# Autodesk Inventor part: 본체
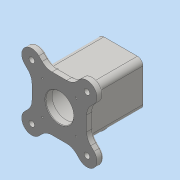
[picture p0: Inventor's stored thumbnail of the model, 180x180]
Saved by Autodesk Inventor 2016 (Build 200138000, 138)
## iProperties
Created: 2019-11
Part Number: 본체
Material: 일반
Document SubType Name: Modeling
Designer: user
Density: 1 g/cm^3
Appearance: 기본값
Author: user
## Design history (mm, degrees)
sketch "스케치1"
  geometry: L1 (49.497, 49.497)-(-49.497, -49.497); L2 (36.77, 62.225)-(-62.225, -36.77); L3 (-36.77, -62.225)-(62.225, 36.77); L4 (-49.497, 49.497)-(49.497, -49.497); L5 (-62.225, 36.77)-(36.77, -62.225); L6 (62.225, -36.77)-(-36.77, 62.225); L7 (0, 0)-(0, -25.456); L8 (49, 49)-(-49, 49); L9 (-49, 49)-(-49, -49); L10 (-49, -49)-(49, -49); L11 (49, -49)-(49, 49); L12 (49, 49)-(-49, -49); L13 (-49, 49)-(49, -49); A1 r 18 centre (49.497, 49.497) between (62.225, 36.77) and (36.77, 62.225); A2 r 18 centre (-49.497, -49.497) between (-62.225, -36.77) and (-36.77, -62.225); A3 r 18 centre (-49.497, 49.497) between (-36.77, 62.225) and (-62.225, 36.77); A4 r 18 centre (49.497, -49.497) between (36.77, -62.225) and (62.225, -36.77)
  constraints: 30 end point, 8 point on circle, 8 tangent, 4 centre point, 4 midpoint, 4 parallel, 1 horizontal, 1 perpendicular, 1 point on line, 1 vertical
  dimensions: "d0" = 70 distance of L7.start L1.end; "d1" = 36 diameter of A2; "d2" = 70 distance of L7.start L4.end; "d3" = 36 diameter of A4; "d4" = 90 deg angle of L4 L1; "d5" = 45 deg angle of L7 L1; "d6" = 98 distance of L9.end L10.end; "d7" = 98 distance of L8.end L9.end
extrude "돌출1" new body sketch "스케치1" distance "d8" = 12; taper "d9" = 0 deg
sketch "스케치2"
  geometry: L1 (-30, -40)-(30, -40); L2 (40, -30)-(40, 30); L3 (30, 40)-(-30, 40); L4 (-40, 30)-(-40, -30); L5 (-40, -40)-(40, 40); L6 (40, -40)-(-40, 40); A1 r 10 centre (-30, 30) between (-30, 40) and (-40, 30); A2 r 10 centre (-30, -30) between (-40, -30) and (-30, -40); A3 r 10 centre (30, -30) between (30, -40) and (40, -30); A4 r 10 centre (30, 30) between (40, 30) and (30, 40); 1 further point
  constraints: 12 end point, 8 point on circle, 8 point on line, 8 tangent, 4 centre point, 3 equal radius, 2 midpoint, 2 parallel, 1 horizontal, 1 perpendicular
  dimensions: "d10" = 80 distance of L6.end L5.end; "d11" = 80 distance of L6.start L5.end; "d56" = 10 radius of A1
extrude "돌출2" join sketch "스케치2" distance "d12" = 98; taper "d13" = 0 deg
sketch "스케치3"
  geometry: 2 further points
  constraints: 1 coincident
hole "구멍1" sketch "스케치3" at (0, 0) diameter "d14" = 50; stored, may be unused: countersink angle "d18" = 90 deg, drill point angle "d20" = 0 deg; dims "d15" = 6, "d16" = 4, "d17" = 2, "d19" = 12
sketch "스케치4"
  geometry: 2 further points
  constraints: 1 coincident
hole "구멍2" sketch "스케치4" at (0, 0) diameter "d21" = 50; stored, may be unused: countersink angle "d25" = 90 deg, drill point angle "d27" = 0 deg; dims "d22" = 6, "d23" = 70, "d24" = 86, "d26" = 12
node "작업 평면1"
sketch "스케치6"
  geometry: L1 (-23.544, 0)-(23.544, 0) reference; C1 r 20 at (0, 61); 1 further point
  constraints: 1 centre point, 1 vertical alignment
  dimensions: "d33" = 40 diameter of C1; "d34" = 61 distance from line of L1 C1.centre
extrude "돌출4" join sketch "스케치6" stored distance "d35" = 30; taper "d36" = 0 deg
sketch "스케치7"
  geometry: C1 r 20 at (0, 0) reference; 2 further points
  constraints: 1 coincident
hole "구멍3" sketch "스케치7" at (0, 0) diameter "d37" = 25; stored, may be unused: countersink angle "d41" = 90 deg, drill point angle "d43" = 0 deg; dims "d38" = 6, "d39" = 30, "d40" = 8, "d42" = 12
sketch "스케치8"
  geometry: L1 (0, 0)-(-49.497, 49.497); L2 (0, 0)-(0, 70); A1 r 70 centre (0, 0) between (-49.497, 49.497) and (0, 70); 1 further point
  constraints: 4 end point, 2 point on circle, 1 centre point, 1 coincident, 1 vertical
  dimensions: "d44" = 140 diameter of A1; "d45" = 45 deg angle of L2 L1
hole "구멍4" sketch "스케치8" at (-49.497, 49.497) diameter "d46" = 10; stored, may be unused: countersink angle "d50" = 90 deg, drill point angle "d52" = 0 deg; dims "d47" = 6, "d48" = 18, "d49" = 4, "d51" = 12
sketch "스케치9"
  geometry: L1 (-30, -30)-(30, -30); L2 (30, -30)-(30, 30); L3 (30, 30)-(-30, 30); L4 (-30, 30)-(-30, -30); L5 (-30, -30)-(30, 30); L6 (30, -30)-(-30, 30); 2 further points
  constraints: 12 end point, 2 midpoint, 2 parallel, 1 coincident, 1 horizontal, 1 perpendicular
  dimensions: "d57" = 60 distance of L3.end L2.end; "d58" = 60 distance of L1.end L2.end
hole "구멍5" sketch "스케치9" at (-30, 30) diameter "d59" = 3.242; stored, may be unused: countersink angle "d63" = 90 deg, drill point angle "d65" = 118 deg; dims "d60" = 8, "d61" = 18, "d62" = 4, "d64" = 10
chamfer "모따기1" distance "d72" = 1; stored, may be unused: second distance "d73" = 2, angle "d74" = 45 deg
fillet "모깎기1" dims "d75" = 3
fillet "모깎기2" dims "d76" = 25
fillet "모깎기3" dims "d77" = 3
fillet "모깎기4" dims "d78" = 3
fillet "모깎기5" dims "d79" = 3
sketch "스케치10" dims "d0" = 70, "d1" = 36, "d2" = 70, "d3" = 36, "d4" = 90 deg, "d5" = 45 deg
  geometry: L1 (0, 0)-(60, 0) reference; C1 r 20 at (30, -49) reference; 2 further points
  constraints: 1 vertical alignment, 1 other
  dimensions: "d80" = 10 distance from line of L1 point (30, -10)
feature "엠보싱1" sketch "스케치10" dims "d0" = 70, "d1" = 36, "d2" = 70, "d3" = 36, "d4" = 90 deg, "d5" = 45 deg, "d81" = 0.5, "d82" = 0
node "작업 평면2"
node "솔리드1"
pattern_circular "원형 패턴1" dims angle "d54" = 360 deg
pattern_linear "직사각형 패턴1" dims "d68" = 60
mirror "대칭1"
other parameters: "d32" = -55
